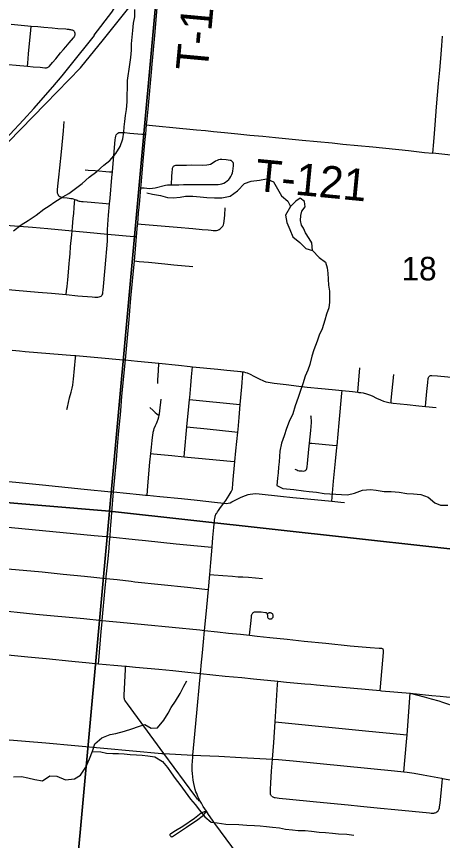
# Model space of a CAD drawing. Extents: x 0 to 1067, y 0 to 440.
# Drawn here: x 400.3 to 445.6, y 79.3 to 167.1 of the extents above; entities that cross this region are included whole.
import ezdxf

# ---------------------------------------------------------------- set-up
doc = ezdxf.new("R2010")
doc.units = 0
for name, color, linetype in [('GM_X_City_Street', 7, 'Continuous'), ('GM_X_Minor_Lake', 7, 'Continuous'), ('GM_X_Minor_River', 7, 'Continuous'), ('GM_X_Rail_Line', 7, 'Continuous'), ('GM_X_Section', 7, 'Continuous'), ('GM_X_Section_Text', 7, 'Continuous'), ('GM_X_State_Route', 7, 'Continuous'), ('GM_X_Township_Road', 7, 'Continuous'), ('GM_X_Township_Road_Text', 7, 'Continuous'), ('GM_X_US_Route', 7, 'Continuous')]:
    doc.layers.add(name, color=color, linetype=linetype)

msp = doc.modelspace()

# ---------------------------------------------------------------- linework, layer by layer
at = {"layer": 'GM_X_City_Street'}
for p, q in [((436.625, 127.063), (436.853, 129.654)), ((415.964, 88.579), (419.054, 88.4))]:
    msp.add_line(p, q, dxfattribs=at)
for points in [[(398.165, 162.1), (401.435, 161.798), (402.055, 161.743), (402.776, 161.679), (403.277, 161.635), (403.341, 161.633), (403.401, 161.633), (403.463, 161.64), (403.526, 161.655), (403.582, 161.676), (403.638, 161.705), (403.688, 161.739), (403.738, 161.782), (403.776, 161.819), (404.102, 162.184), (404.446, 162.575), (404.708, 162.893), (404.971, 163.209), (405.279, 163.58), (405.513, 163.868), (405.865, 164.27), (406.344, 164.818), (406.406, 164.908), (406.453, 164.981), (406.474, 165.02), (406.489, 165.056), (406.506, 165.133), (406.513, 165.197), (406.513, 165.261), (406.508, 165.306), (406.498, 165.352), (406.482, 165.409), (406.456, 165.464), (406.423, 165.514), (406.37, 165.561), (406.307, 165.598), (406.244, 165.624), (406.174, 165.644), (406.074, 165.666), (406, 165.679), (405.938, 165.687), (405.876, 165.695), (405.792, 165.703), (405.673, 165.713), (405.508, 165.726), (404.674, 165.795), (404.081, 165.847), (403.188, 165.926), (402.558, 165.981), (401.848, 166.045), (399.699, 166.237)], [(401.435, 161.798), (401.465, 162.115), (401.558, 163.113), (401.801, 165.629), (401.848, 166.045)], [(405.321, 155.907), (405.224, 154.895), (405.011, 152.677), (404.837, 150.974), (404.746, 149.971), (404.649, 149.01), (404.613, 148.63), (404.604, 148.489), (404.604, 148.39), (404.609, 148.321), (404.622, 148.249), (404.663, 148.149), (404.723, 148.062), (404.779, 147.998), (404.875, 147.925), (404.94, 147.886), (405.008, 147.854), (405.094, 147.831), (405.212, 147.813), (405.684, 147.777), (405.871, 147.749), (406.052, 147.718), (406.193, 147.686), (406.311, 147.654), (406.5, 147.597), (406.628, 147.554), (406.747, 147.509), (406.851, 147.468), (406.955, 147.431), (407.067, 147.402), (407.21, 147.382), (407.373, 147.368), (408.24, 147.295), (409.815, 147.164), (410.177, 147.134)], [(409.277, 137.301), (409.351, 137.366), (409.403, 137.448), (409.449, 137.561), (409.481, 137.713), (409.509, 137.937), (409.716, 140.334), (409.949, 143.157), (409.965, 143.509), (409.957, 143.91), (409.965, 144.361), (409.989, 144.938), (410.07, 145.937), (410.177, 147.134), (410.232, 147.753), (410.435, 149.944), (410.486, 150.534), (410.743, 153.559), (410.779, 153.951), (410.809, 154.165), (410.842, 154.345), (410.898, 154.493), (410.955, 154.571), (411.055, 154.664), (411.178, 154.722), (411.316, 154.744), (411.45, 154.752), (411.816, 154.733), (412.359, 154.679), (413.621, 154.574), (414.035, 154.545)], [(413.517, 148.85), (413.873, 148.824), (414.435, 148.783), (414.76, 148.799), (415.048, 148.855), (416.138, 149.107), (416.362, 149.144), (416.662, 149.165), (416.727, 149.165), (417.558, 149.176), (418.041, 149.194), (418.751, 149.194), (419.16, 149.181), (421.393, 149.177), (421.76, 149.193), (421.975, 149.224), (422.149, 149.271), (422.35, 149.351), (422.539, 149.455), (422.712, 149.584), (422.873, 149.731), (422.988, 149.867), (423.107, 150.049), (423.221, 150.276), (423.282, 150.444), (423.321, 150.619), (423.382, 151.17), (423.389, 151.349), (423.376, 151.449), (423.342, 151.541), (423.287, 151.62), (423.213, 151.686), (423.127, 151.735), (423.031, 151.763), (422.593, 151.818), (422.152, 151.858), (421.973, 151.853), (421.8, 151.82), (421.635, 151.758), (421.478, 151.672), (421.105, 151.421), (420.931, 151.336), (420.745, 151.277), (420.554, 151.248), (420.065, 151.232), (418.947, 151.24), (418.391, 151.236), (417.757, 151.233), (417.427, 151.228), (417.315, 151.222), (417.199, 151.216), (417.113, 151.199), (417.027, 151.159), (416.964, 151.113), (416.906, 151.038), (416.878, 150.964), (416.856, 150.884), (416.849, 150.831), (416.808, 150.468), (416.784, 150.097), (416.727, 149.165)], [(407.601, 150.756), (407.912, 150.735), (408.652, 150.674), (410.191, 150.556), (410.486, 150.534)], [(405.558, 137.468), (405.605, 137.852), (405.652, 138.339), (405.721, 139.029), (405.798, 139.844), (405.879, 140.781), (405.911, 141.143), (405.973, 141.807), (406.037, 142.58), (406.15, 143.84), (406.184, 144.271), (406.223, 144.699), (406.256, 145.129), (406.307, 145.615), (406.362, 146.115), (406.421, 146.745), (406.463, 147.189), (406.5, 147.597)], [(413.178, 145.019), (413.538, 144.986), (417.392, 144.637), (419.064, 144.494), (420.03, 144.403), (420.7, 144.349), (421, 144.319), (421.214, 144.297), (421.408, 144.3), (421.555, 144.308), (421.7, 144.337), (421.839, 144.39), (421.967, 144.466), (422.081, 144.563), (422.179, 144.675), (422.242, 144.767), (422.306, 144.881), (422.35, 145.032), (422.389, 145.288), (422.448, 145.919), (422.49, 146.7)], [(397.164, 145.035), (398.622, 144.91), (401.988, 144.639), (403.61, 144.497), (406.184, 144.271)], [(406.184, 144.271), (407.779, 144.132), (409.957, 143.91)], [(409.957, 143.91), (412.783, 143.664), (413.062, 143.641)], [(412.836, 141.05), (413.318, 141.004), (414.32, 140.908), (416.063, 140.734), (417.029, 140.639), (419.034, 140.443)], [(395.418, 138.347), (395.767, 138.317), (397.328, 138.185), (402.576, 137.729), (403.985, 137.62), (405.558, 137.468), (406.789, 137.35), (408.315, 137.216), (408.613, 137.201), (408.945, 137.206), (409.064, 137.219), (409.195, 137.252), (409.277, 137.301)], [(399.801, 131.54), (400.579, 131.474), (401.21, 131.418), (406.431, 130.978), (406.577, 130.965), (408.947, 130.756), (411.643, 130.52), (411.873, 130.5), (412.497, 130.44), (413.164, 130.38), (415.445, 130.154), (417.508, 129.938), (418.768, 129.809), (419.033, 129.783), (421.698, 129.525), (422.662, 129.424), (423.811, 129.298), (424.145, 129.262), (424.202, 129.255), (424.38, 129.232)], [(405.646, 125.223), (405.717, 125.487), (405.927, 126.466), (406.083, 127.079), (406.202, 127.507), (406.262, 127.815), (406.313, 128.157), (406.339, 128.448), (406.553, 130.716), (406.577, 130.965)], [(415.308, 127.977), (415.337, 128.382), (415.4, 129.341), (415.445, 130.154)], [(418.12, 120.174), (418.161, 120.604), (418.427, 123.369), (418.636, 125.545), (418.706, 126.298), (418.726, 126.509), (418.835, 127.773), (418.924, 128.7), (419.033, 129.783)], [(420.296, 101.69), (420.496, 103.779), (420.641, 105.304), (420.713, 106.049), (420.855, 107.647), (420.968, 108.917), (421.107, 110.558), (421.186, 111.586), (421.294, 112.666), (421.374, 113.407), (421.402, 113.671), (421.415, 113.768), (421.435, 113.862), (421.466, 113.955), (421.511, 114.049), (421.554, 114.128), (421.59, 114.185), (421.673, 114.308), (421.799, 114.478), (421.937, 114.671), (422.212, 115.051), (422.348, 115.239), (422.55, 115.517), (422.916, 116.089), (423.147, 116.449), (423.187, 116.532), (423.218, 116.593), (423.24, 116.657), (423.263, 116.737), (423.278, 116.816), (423.287, 116.882), (423.292, 116.945), (423.307, 117.146), (423.32, 117.317), (423.357, 117.75), (423.491, 119.289), (423.529, 119.673), (423.642, 120.823), (423.844, 122.823), (423.87, 123.084), (423.996, 124.372), (424.107, 125.764), (424.257, 127.628), (424.368, 129.059), (424.38, 129.232)], [(424.38, 129.232), (424.474, 129.221), (424.65, 129.18), (424.822, 129.126), (425.16, 128.983), (425.556, 128.78), (426.119, 128.485), (426.562, 128.28), (426.812, 128.188), (427.07, 128.124), (427.7, 128.027), (428.997, 127.871), (430.33, 127.719), (431.218, 127.613), (432.738, 127.444), (433.89, 127.34), (434.955, 127.235), (436.041, 127.127), (436.625, 127.063), (436.743, 127.05), (436.943, 127.02), (437.182, 126.983), (437.541, 126.901), (437.856, 126.802), (438.162, 126.676), (438.627, 126.445), (439.033, 126.248), (439.349, 126.124), (439.639, 126.039), (439.935, 125.977), (440.161, 125.946), (440.381, 125.915), (441.864, 125.756), (443.123, 125.614), (443.831, 125.541), (444.971, 125.423)], [(440.161, 125.946), (440.188, 126.229), (440.449, 128.967)], [(443.831, 125.541), (443.87, 125.958), (443.98, 127.147), (444.089, 128.111), (444.125, 128.52), (444.151, 128.63), (444.181, 128.697), (444.225, 128.757), (444.281, 128.805), (444.382, 128.851), (444.492, 128.862), (445.124, 128.802), (446.199, 128.688), (447.163, 128.585), (453.978, 127.908), (454.048, 127.901)], [(433.85, 115.459), (433.89, 115.875), (434.043, 117.581), (434.246, 119.731), (434.387, 121.177), (434.407, 121.383), (434.646, 123.808), (434.932, 126.977), (434.955, 127.235)], [(414.854, 122.927), (414.885, 123.025), (414.949, 123.186), (415.088, 123.527), (415.173, 123.731), (415.239, 123.9), (415.278, 123.999), (415.315, 124.098), (415.351, 124.196), (415.424, 124.427), (415.457, 124.571), (415.499, 124.764), (415.543, 125.089), (415.662, 126.311)], [(418.706, 126.298), (419.052, 126.264), (423.712, 125.803), (424.107, 125.764)], [(414.472, 125.43), (414.815, 125.107), (415.047, 124.905), (415.221, 124.763), (415.457, 124.571)], [(429.91, 118.874), (430.114, 118.782), (430.217, 118.739), (430.362, 118.705), (430.698, 118.672), (430.848, 118.668), (430.957, 118.687), (431.056, 118.735), (431.112, 118.783), (431.156, 118.843), (431.202, 118.946), (431.245, 119.114), (431.279, 119.456), (431.402, 120.99), (431.468, 121.652), (431.602, 122.997), (431.679, 123.853), (431.685, 124.114), (431.664, 124.281), (431.638, 124.427), (431.613, 124.556)], [(414.175, 116.089), (414.218, 116.571), (414.265, 117.09), (414.475, 119.613), (414.57, 120.523), (414.641, 121.201), (414.719, 121.938), (414.789, 122.522), (414.813, 122.698), (414.832, 122.824), (414.854, 122.927)], [(418.427, 123.369), (418.771, 123.34), (420.592, 123.158), (423.532, 122.855), (423.844, 122.823)], [(431.468, 121.652), (431.724, 121.629), (433.927, 121.435), (434.407, 121.383)], [(414.57, 120.523), (414.87, 120.494), (416.811, 120.306), (418.12, 120.174), (418.476, 120.139), (419.66, 120.023), (423.065, 119.715), (423.529, 119.673)], [(398.981, 117.579), (400.21, 117.465), (403.036, 117.184), (407.49, 116.739), (410.362, 116.469), (410.611, 116.445)], [(410.611, 116.445), (413.358, 116.171), (414.007, 116.106), (414.175, 116.089), (415.524, 115.954), (417.859, 115.724), (419.526, 115.557), (421.343, 115.367), (422.348, 115.239)], [(422.348, 115.239), (422.413, 115.23), (422.631, 115.223), (422.809, 115.24), (423.013, 115.297), (423.211, 115.383), (423.784, 115.674), (424.215, 115.88), (424.663, 116.07), (424.949, 116.17), (425.173, 116.221), (425.438, 116.252), (425.741, 116.259), (426.117, 116.237), (428.377, 115.979), (429.711, 115.844), (431.27, 115.706), (433.85, 115.459), (434.83, 115.365), (435.215, 115.328)], [(373.937, 115.042), (374.425, 114.997), (375.645, 114.889), (378.78, 114.612), (379.021, 114.591), (382.71, 114.268), (383.853, 114.166), (384.189, 114.124), (386.417, 113.917), (388.447, 113.728), (390.523, 113.524), (394.165, 113.168), (394.515, 113.136), (398.504, 112.778), (398.648, 112.765), (408.548, 111.817), (410.23, 111.667), (412.922, 111.384), (414.026, 111.268), (417.287, 110.919), (420.686, 110.598), (421.107, 110.558)], [(399.342, 108.265), (402.999, 107.914), (405.231, 107.677), (407.525, 107.467), (409.813, 107.233), (410.999, 107.104), (412.468, 106.929), (412.875, 106.88), (418.47, 106.29), (420.314, 106.094), (420.713, 106.049)], [(420.855, 107.647), (421.301, 107.614), (422.255, 107.543), (423.264, 107.456), (423.881, 107.412), (424.386, 107.386), (424.994, 107.352), (426.464, 107.221)], [(397.657, 103.904), (402.338, 103.412), (407.438, 102.944), (409.404, 102.76)], [(425.081, 101.173), (425.118, 101.506), (425.218, 102.415), (425.295, 103.107), (425.317, 103.267), (425.347, 103.393), (425.368, 103.453), (425.402, 103.505), (425.456, 103.572), (425.501, 103.606), (425.557, 103.638), (425.605, 103.658), (425.664, 103.674), (425.727, 103.684), (425.921, 103.685), (426.335, 103.654), (426.785, 103.608), (426.828, 103.599), (426.875, 103.581), (426.915, 103.552), (426.947, 103.519), (426.969, 103.476), (426.981, 103.423), (426.99, 103.317), (426.993, 103.218), (427.002, 103.149), (427.017, 103.093), (427.038, 103.042), (427.077, 102.988), (427.128, 102.949), (427.175, 102.925), (427.241, 102.91), (427.292, 102.908), (427.343, 102.91), (427.388, 102.92), (427.436, 102.937), (427.484, 102.964), (427.513, 102.989), (427.546, 103.024), (427.572, 103.059), (427.591, 103.099), (427.608, 103.147), (427.614, 103.204), (427.615, 103.251), (427.606, 103.308), (427.58, 103.38), (427.556, 103.417), (427.52, 103.452), (427.472, 103.488), (427.436, 103.509), (427.4, 103.526), (427.34, 103.547), (427.268, 103.556), (427.218, 103.553), (427.175, 103.547), (427.131, 103.535), (427.077, 103.514), (427.023, 103.479)], [(409.404, 102.76), (412.055, 102.504), (413.9, 102.327), (419.804, 101.753), (420.296, 101.69)], [(419.858, 97.114), (419.972, 98.294), (420.04, 98.945), (420.116, 99.677), (420.197, 100.454), (420.296, 101.69)], [(420.296, 101.69), (421.685, 101.525), (422.834, 101.405), (424.133, 101.276), (425.081, 101.173), (425.912, 101.083), (427.247, 100.945), (429.102, 100.756), (430.918, 100.558), (433.217, 100.316), (435.814, 100.053), (437.924, 99.877), (438.894, 99.806), (439.033, 99.799), (439.144, 99.784), (439.212, 99.765), (439.271, 99.734)], [(439.021, 95.276), (439.052, 95.67), (439.344, 99.35), (439.352, 99.467), (439.347, 99.571), (439.334, 99.64), (439.307, 99.698), (439.271, 99.734)], [(419.844, 83.492), (419.741, 83.549), (419.653, 83.623), (419.565, 83.711), (419.463, 83.83), (419.262, 84.095), (415.964, 88.579), (412.086, 93.853), (411.884, 94.154), (411.824, 94.25), (411.785, 94.342), (411.76, 94.413), (411.745, 94.489), (411.738, 94.553), (411.736, 94.625), (411.741, 94.78), (411.869, 97.533), (411.885, 97.878)], [(427.443, 84.034), (427.394, 84.089), (427.363, 84.155), (427.339, 84.224), (427.322, 84.328), (427.315, 84.425), (427.315, 84.557), (427.318, 84.751), (427.359, 85.458), (427.444, 86.691), (427.54, 87.969), (427.681, 89.756), (427.832, 91.934), (428.08, 95.928), (428.101, 96.275)], [(441.537, 86.636), (441.811, 89.809), (441.868, 90.573), (442.198, 94.991)], [(427.832, 91.934), (428.174, 91.9), (437.426, 90.99), (441.48, 90.61), (441.868, 90.573)], [(398.652, 90.116), (403.385, 89.699), (415.756, 88.59), (415.964, 88.579)], [(419.054, 88.4), (419.907, 88.362), (421.837, 88.277), (424.211, 88.161), (427.54, 87.969)], [(427.54, 87.969), (428.165, 87.921), (429.724, 87.787), (440.527, 86.741), (441.537, 86.636), (441.88, 86.594), (442.641, 86.476), (443.587, 86.308), (445.546, 85.942), (445.63, 85.926), (447.436, 85.576), (448.043, 85.462), (448.382, 85.406), (448.645, 85.376), (448.887, 85.355), (449.253, 85.365)], [(427.443, 84.034), (427.502, 83.985), (427.568, 83.947), (427.64, 83.916), (427.73, 83.892), (427.827, 83.871), (428.241, 83.817), (429.351, 83.703), (431.865, 83.463), (434.457, 83.204), (435.606, 83.093), (436.9, 82.966), (439.047, 82.759), (440.565, 82.613), (444.26, 82.237), (444.448, 82.225), (444.632, 82.223), (444.725, 82.231), (444.804, 82.242), (444.878, 82.265), (444.955, 82.299), (445.047, 82.353), (445.129, 82.424), (445.171, 82.47), (445.22, 82.54), (445.254, 82.601), (445.282, 82.675), (445.308, 82.769), (445.334, 82.89), (445.356, 83.053), (445.391, 83.332), (445.491, 84.333), (445.591, 85.479), (445.63, 85.926)], [(416.658, 79.792), (416.635, 79.85), (416.63, 79.919), (416.645, 79.977), (416.676, 80.014), (416.712, 80.041), (417.22, 80.359), (417.976, 80.832), (419.231, 81.697), (419.954, 82.239), (420.039, 82.289), (420.129, 82.328), (420.219, 82.366), (420.3, 82.391), (420.49, 82.435)], [(416.658, 79.792), (416.697, 79.749), (416.75, 79.722), (416.823, 79.712), (416.885, 79.722), (418.367, 80.709), (419.568, 81.533), (420.045, 81.892), (420.177, 82.005), (420.269, 82.099), (420.342, 82.182), (420.402, 82.272), (420.49, 82.435)]]:
    msp.add_lwpolyline(points, dxfattribs=at)
at = {"layer": 'GM_X_Minor_Lake'}
for points in [[(431.78, 142.153), (431.739, 142.975), (431.447, 143.456), (431.066, 144.05), (430.843, 144.53), (430.642, 144.872), (430.532, 145.351), (430.537, 145.897), (430.654, 146.351), (430.998, 146.826), (430.935, 147.395), (430.484, 147.74), (430.004, 147.402), (429.455, 146.838)], [(429.455, 146.838), (428.925, 145.932), (429.078, 145.158), (429.367, 144.405), (429.701, 143.606), (430.445, 143.008), (431.075, 142.366), (431.78, 142.153)]]:
    msp.add_lwpolyline(points, dxfattribs=at)
at = {"layer": 'GM_X_Minor_River'}
for points in [[(399.946, 144.272), (400.769, 144.903), (401.522, 145.375), (402.366, 145.937), (403.166, 146.567), (403.736, 146.927), (404.353, 147.331), (405.197, 147.871), (405.836, 148.253), (406.681, 148.883), (407.252, 149.288), (408.006, 149.965), (408.829, 150.595), (409.583, 151.272), (410.2, 151.767), (410.842, 152.49), (411.325, 153.237), (411.581, 154.054), (411.7, 154.781), (411.751, 155.349), (411.823, 155.917), (411.897, 156.531), (411.97, 157.19), (412.045, 158.009), (412.074, 158.805), (412.079, 159.396), (412.109, 160.261), (412.327, 161.965), (412.447, 162.715), (412.521, 163.51), (412.527, 164.17), (412.578, 164.875), (412.652, 165.602), (412.727, 166.398), (412.891, 167.056), (412.875, 167.853)], [(414.167, 148.301), (414.756, 148.16), (415.617, 148.016), (416.365, 147.806), (416.955, 147.778), (417.704, 147.841), (418.273, 147.95), (419.067, 147.966), (419.839, 147.892), (420.542, 147.818), (421.359, 147.766), (422.153, 147.76), (423.04, 147.935), (423.817, 148.521), (424.549, 149.311), (425.278, 149.533), (426.141, 149.64), (426.892, 149.816), (427.638, 149.491), (428.086, 148.737), (428.511, 147.983), (429.164, 147.409), (429.455, 146.838), (428.925, 145.932), (429.078, 145.158), (429.367, 144.405), (429.701, 143.606), (430.445, 143.008), (431.075, 142.366), (431.78, 142.153), (432.52, 141.4), (433.197, 140.916), (433.351, 140.324), (433.415, 139.755), (433.455, 139.117), (433.495, 138.457), (433.603, 137.842), (433.621, 137.228), (433.616, 136.659), (433.543, 136.045), (433.288, 135.365), (433.101, 134.729), (432.821, 133.822), (432.498, 133.142), (432.311, 132.506), (431.94, 131.576), (431.73, 130.895), (431.496, 130.033), (431.287, 129.42), (431.009, 128.763), (430.752, 127.946), (430.496, 127.151), (430.286, 126.493), (429.961, 125.631), (429.705, 124.769), (429.312, 123.93), (429.033, 123.205), (428.777, 122.41), (428.498, 121.639), (428.333, 120.798), (428.283, 120.23), (428.232, 119.662), (428.16, 119.094), (428.132, 118.48), (428.082, 117.911), (428.007, 117.138), (428.64, 116.792), (429.82, 116.692), (430.84, 116.547), (431.453, 116.497), (432.224, 116.4), (433.04, 116.28), (433.652, 116.229), (434.265, 116.202), (434.878, 116.174), (435.513, 116.147), (436.263, 116.3), (437.106, 116.635), (437.969, 116.696), (438.581, 116.623), (439.42, 116.502), (440.192, 116.474), (441.031, 116.399), (441.847, 116.279), (442.551, 116.227), (443.322, 116.153), (444.114, 115.897), (444.835, 115.277), (445.424, 115.045), (446.218, 115.016)], [(399.967, 86.078), (400.807, 86.14), (401.487, 85.975), (402.234, 85.81), (403.028, 85.667), (403.804, 86.207), (404.575, 86.156), (405.503, 85.762), (406.434, 85.891), (407.096, 86.272), (407.648, 87.132), (408.041, 87.994), (408.366, 88.833), (408.599, 89.605), (409.353, 90.236), (410.264, 90.593), (410.833, 90.702), (411.788, 90.945), (412.562, 91.211), (413.268, 91.456), (413.928, 91.656), (414.605, 91.264), (415.287, 91.304), (415.952, 92.117), (416.435, 92.865), (416.758, 93.476), (417.194, 94.133), (417.7, 94.97), (418.093, 95.741), (418.415, 96.33)], [(408.345, 88.781), (409.25, 88.758), (409.862, 88.617), (410.543, 88.588), (411.133, 88.584), (411.745, 88.533), (412.381, 88.483), (413.061, 88.432), (413.651, 88.405), (414.241, 88.332), (415.012, 88.235), (415.825, 87.728), (416.342, 87.087), (416.745, 86.515), (417.172, 85.92), (417.666, 85.279), (418.811, 83.723), (419.305, 83.128), (419.777, 82.555), (420.339, 81.823), (421.015, 81.249), (421.628, 81.176), (422.557, 81.032), (423.964, 81.021), (424.804, 80.946), (425.62, 80.894), (426.21, 80.866), (426.891, 80.793), (427.549, 80.742), (428.297, 80.645), (428.909, 80.527), (429.657, 80.43), (430.27, 80.379), (431.019, 80.373), (431.676, 80.3), (432.515, 80.202), (433.196, 80.151), (433.922, 80.077), (434.58, 80.027), (435.465, 79.974), (436.19, 79.878)]]:
    msp.add_lwpolyline(points, dxfattribs=at)
at = {"layer": 'GM_X_Rail_Line'}
for points in [[(408.56, 165.102), (410.412, 167.557), (412.438, 170.807), (417.322, 178.232), (419.985, 182.992), (422.458, 187.815), (426.199, 195.113), (440.657, 223.354), (457.117, 255.21), (463.098, 267.381), (466.122, 273.22), (468.95, 277.714), (472.098, 282.339), (474.93, 286.228), (477.916, 290.371), (491.276, 306.364), (506.266, 324.251), (534.378, 357.191), (539, 362.723)], [(389.458, 143.485), (392.267, 146.546), (395.371, 149.61), (403.354, 157.796), (407.091, 161.624), (409.522, 164.625), (412.954, 168.924)], [(389.459, 144.278), (390.77, 145.605), (392.599, 147.461), (395.341, 150.233), (397.597, 152.528), (399.565, 154.533), (401.022, 156.077), (402.126, 157.297), (404.132, 159.609), (405.12, 160.763), (405.985, 161.836), (408.574, 165.069)]]:
    msp.add_lwpolyline(points, dxfattribs=at)
at = {"layer": 'GM_X_Section'}
for points in [[(353.183, 178.942), (415.565, 173.729), (410.18, 114.397), (348.264, 119.585)], [(476.775, 167.814), (470.491, 107.701), (410.18, 114.397), (415.565, 173.729)], [(410.18, 114.397), (404.583, 52.958), (342.16, 58.91), (348.264, 119.585)], [(410.18, 114.397), (470.491, 107.701), (464.499, 47.289), (404.583, 52.958)]]:
    msp.add_lwpolyline(points, close=True, dxfattribs=at)
at = {"layer": 'GM_X_State_Route'}
for p, q in [((411.885, 97.878), (412.004, 97.867)), ((439.021, 95.276), (439.141, 95.265)), ((439.141, 95.265), (442.198, 94.991))]:
    msp.add_line(p, q, dxfattribs=at)
for points in [[(397.191, 99.278), (397.527, 99.246), (399.344, 99.072), (401.489, 98.866), (403.421, 98.681), (406.181, 98.417), (408.023, 98.236), (409.014, 98.144)], [(409.014, 98.144), (410.625, 97.995), (411.885, 97.878)], [(412.004, 97.867), (412.956, 97.779), (415.425, 97.55), (416.906, 97.412), (418.535, 97.248), (419.858, 97.114)], [(419.959, 83.291), (419.844, 83.492), (419.697, 83.773), (419.584, 84.006), (419.464, 84.299), (419.386, 84.508), (419.31, 84.756), (419.225, 85.071), (419.159, 85.37), (419.089, 85.73), (419.04, 86.074), (419.004, 86.458), (418.989, 86.751), (418.986, 87.014), (418.984, 87.317), (419.034, 88.18), (419.054, 88.4), (419.257, 90.633), (419.506, 93.306), (419.747, 95.979), (419.858, 97.114)], [(419.858, 97.114), (422.498, 96.827), (424.279, 96.663), (425.506, 96.54), (428.101, 96.275)], [(428.101, 96.275), (429.025, 96.19), (430.994, 96.012), (431.633, 95.946)], [(431.633, 95.946), (432.215, 95.885), (433.404, 95.78), (439.021, 95.276)], [(442.198, 94.991), (443.688, 94.605), (444.446, 94.408), (445.242, 94.187), (445.66, 94.058), (446.189, 93.871), (446.583, 93.724), (446.937, 93.577), (447.445, 93.363), (448.001, 93.109), (448.465, 92.863), (448.949, 92.606), (449, 92.585), (449.054, 92.568), (449.144, 92.547), (449.373, 92.511)], [(423.792, 77.851), (421.397, 81.115), (420.732, 82.062), (420.49, 82.435), (420.162, 82.939), (419.959, 83.291)]]:
    msp.add_lwpolyline(points, dxfattribs=at)
at = {"layer": 'GM_X_Township_Road'}
for p, q in [((414.035, 154.545), (414.125, 155.558)), ((423.855, 154.581), (425.106, 154.459))]:
    msp.add_line(p, q, dxfattribs=at)
for points in [[(414.681, 161.566), (414.686, 161.625), (415.002, 165.07), (415.141, 166.741), (415.3, 168.484), (415.395, 169.407)], [(444.604, 152.535), (444.714, 153.737), (444.796, 154.631), (444.87, 155.56), (445.019, 157.454), (445.222, 159.942), (445.352, 161.389), (445.459, 162.614), (445.573, 163.988), (445.658, 165.009)], [(414.125, 155.558), (414.177, 156.142), (414.277, 157.218), (414.681, 161.566)], [(414.125, 155.558), (414.385, 155.532), (415.449, 155.423), (416.938, 155.282), (419.454, 155.035), (420.404, 154.939), (421.27, 154.847), (422.422, 154.727), (423.498, 154.615), (423.855, 154.581)], [(413.517, 148.85), (413.542, 149.128), (413.771, 151.689), (413.988, 154.027), (414.035, 154.545)], [(425.106, 154.459), (426.504, 154.332), (427.841, 154.212), (430.708, 153.932), (433.892, 153.621), (435.041, 153.499), (438.234, 153.197), (442.019, 152.813), (443.723, 152.614), (444.604, 152.535)], [(457.777, 151.218), (456.296, 151.357), (454.776, 151.503), (453.257, 151.655), (450.813, 151.91), (447.778, 152.212), (446.52, 152.337), (444.604, 152.535)], [(413.178, 145.019), (413.275, 146.159), (413.331, 146.752), (413.394, 147.496), (413.517, 148.85)], [(413.062, 143.641), (413.164, 144.86), (413.178, 145.019)], [(412.836, 141.05), (412.915, 141.89), (413.062, 143.641)], [(411.873, 130.5), (412.256, 134.814), (412.344, 135.741), (412.461, 137.077), (412.836, 141.05)], [(410.611, 116.445), (410.677, 117.234), (410.904, 119.867), (411.033, 121.275), (411.149, 122.574), (411.244, 123.649), (411.335, 124.651), (411.404, 125.58), (411.499, 126.656), (411.873, 130.5)], [(410.23, 111.667), (410.297, 112.519), (410.352, 113.299), (410.425, 114.264), (410.611, 116.445)], [(409.813, 107.233), (409.829, 107.388), (409.956, 108.686), (410.019, 109.314), (410.127, 110.448), (410.185, 111.113), (410.23, 111.667)], [(409.404, 102.76), (409.717, 106.239), (409.813, 107.233)], [(409.014, 98.144), (409.042, 98.481), (409.303, 101.574), (409.391, 102.613), (409.404, 102.76)]]:
    msp.add_lwpolyline(points, dxfattribs=at)
at = {"layer": 'GM_X_US_Route'}
for p, q in [((411.885, 97.878), (412.004, 97.867)), ((439.021, 95.276), (439.141, 95.265)), ((439.141, 95.265), (442.198, 94.991))]:
    msp.add_line(p, q, dxfattribs=at)
for points in [[(397.191, 99.278), (397.527, 99.246), (399.344, 99.072), (401.489, 98.866), (403.421, 98.681), (406.181, 98.417), (408.023, 98.236), (409.014, 98.144)], [(409.014, 98.144), (410.625, 97.995), (411.885, 97.878)], [(412.004, 97.867), (412.956, 97.779), (415.425, 97.55), (416.906, 97.412), (418.535, 97.248), (419.858, 97.114)], [(419.858, 97.114), (422.498, 96.827), (424.279, 96.663), (425.506, 96.54), (428.101, 96.275)], [(428.101, 96.275), (429.025, 96.19), (430.994, 96.012), (431.633, 95.946)], [(431.633, 95.946), (432.215, 95.885), (433.404, 95.78), (439.021, 95.276)], [(442.198, 94.991), (444.496, 94.77), (445.378, 94.69)], [(445.378, 94.69), (446.083, 94.627), (448.667, 94.394), (449.481, 94.317), (449.779, 94.289)]]:
    msp.add_lwpolyline(points, dxfattribs=at)

# ---------------------------------------------------------------- texts
at = {"layer": 'GM_X_Section_Text'}
msp.add_text('18', height=2.5114, rotation=0.00001, dxfattribs=at).set_placement((441.279, 138.976))
at = {"layer": 'GM_X_Township_Road_Text'}
for s, rotation, p in [('T-126', 84.72983, (420.626, 161.194)), ('T-121', 354.46528, (425.584, 148.536))]:
    msp.add_text(s, height=3.4091, rotation=rotation, dxfattribs=at).set_placement(p)

doc.saveas('drawing.dxf')
